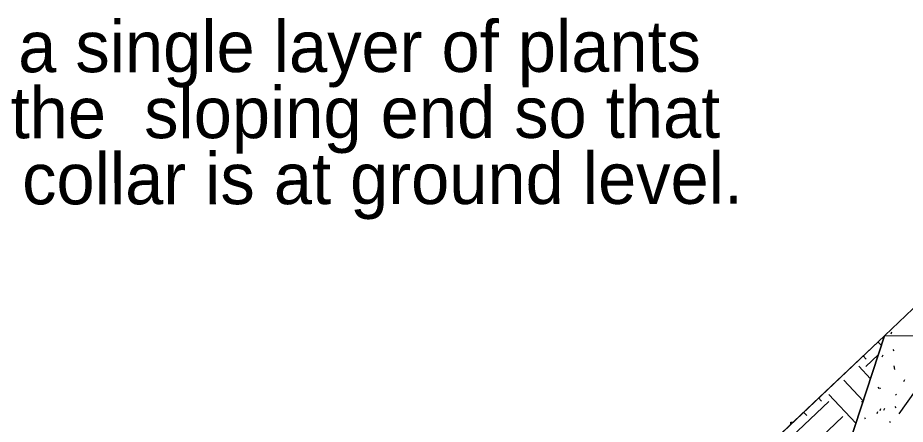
# Model space of a CAD drawing. Extents: x 1728110 to 1729925, y 1284214 to 1285339.
# Drawn here: x 1728313.6 to 1728432.8, y 1284651.8 to 1284706.3 of the extents above; entities that cross this region are included whole.
import ezdxf

# ---------------------------------------------------------------- set-up
doc = ezdxf.new("R2010")
doc.units = 0
doc.layers.add('Reforestation Detail CELL', color=7, linetype='Continuous')

msp = doc.modelspace()

# ---------------------------------------------------------------- linework, layer by layer
at = {"layer": 'Reforestation Detail CELL'}
for p, q in [((1728417.7, 1284626.03), (1728429.97, 1284663.64)), ((1728429.97, 1284663.64), (1728417.7, 1284626.03)), ((1728429.99, 1284663.64), (1728421.19, 1284655.33)), ((1728429.95, 1284663.64), (1728553.13, 1284663.73)), ((1728430.85, 1284663.9), (1728430.96, 1284664.15)), ((1728429.51, 1284662.38), (1728429.1, 1284662.82)), ((1728427.51, 1284660.49), (1728427.1, 1284660.93)), ((1728427.48, 1284659.52), (1728429.14, 1284661.08)), ((1728429.66, 1284660.81), (1728429.78, 1284661.06)), ((1728431.11, 1284661.79), (1728431.22, 1284661.62)), ((1728428.09, 1284657.87), (1728426.51, 1284659.54)), ((1728431.24, 1284659.6), (1728431.3, 1284659.09)), ((1728427.12, 1284654.89), (1728424.5, 1284657.65)), ((1728432.59, 1284657.49), (1728432.7, 1284657.75)), ((1728429.09, 1284656.72), (1728429.2, 1284656.56)), ((1728429.29, 1284656.67), (1728429.4, 1284656.51)), ((1728371.68, 1284608.63), (1728421.2, 1284655.36)), ((1728417.5, 1284650.09), (1728422.51, 1284654.82)), ((1728420.59, 1284654.79), (1728420.59, 1284654.79)), ((1728421.53, 1284654.84), (1728421.12, 1284655.29)), ((1728426.14, 1284651.9), (1728422.5, 1284655.76)), ((1728426.94, 1284654.87), (1728426.97, 1284654.62)), ((1728431.45, 1284655.81), (1728431.56, 1284655.64)), ((1728429.39, 1284653.61), (1728429.5, 1284653.87)), ((1728429.88, 1284653.65), (1728430, 1284653.9)), ((1728431.38, 1284654.12), (1728431.5, 1284653.95)), ((1728419.53, 1284652.95), (1728419.11, 1284653.4)), ((1728419.23, 1284653.51), (1728419.23, 1284653.5)), ((1728419.39, 1284648.08), (1728424.4, 1284652.81)), ((1728427.27, 1284652.67), (1728427.38, 1284652.5)), ((1728428.98, 1284653.2), (1728429.09, 1284653.45)), ((1728430.64, 1284652.16), (1728430.75, 1284651.99))]:
    msp.add_line(p, q, dxfattribs=at)
for points in [[(1728435.66, 1284669.01), (1728430, 1284663.65)], [(1728429.99, 1284663.64), (1728411.32, 1284645.95)], [(1728435.29, 1284657.93), (1728431.9, 1284653.16)], [(1728417.4, 1284651.78), (1728417.4, 1284652.05), (1728417.69, 1284652.05)]]:
    msp.add_lwpolyline(points, dxfattribs=at)

# ---------------------------------------------------------------- texts
for s, p in [('4. Place a single layer of plants ', (1728277.81, 1284698.95)), (' against the  sloping end so that ', (1728277.82, 1284690.09)), (' the root collar is at ground level.', (1728277.83, 1284681.23))]:
    msp.add_text(s, height=6.8898, rotation=0.0429, dxfattribs=at).set_placement(p)

doc.saveas('drawing.dxf')
